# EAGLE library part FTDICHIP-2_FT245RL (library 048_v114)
USB FIFO Controller 4th Generation USB Controller (USB <-> Parallel) - FIFO
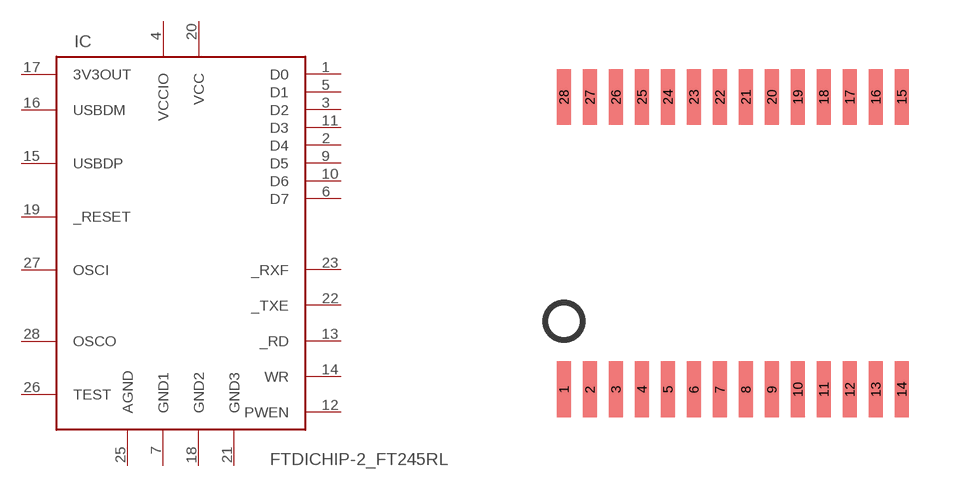
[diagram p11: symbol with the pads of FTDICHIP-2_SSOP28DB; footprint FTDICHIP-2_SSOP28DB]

Designator prefix IC

## FTDICHIP-2_FT245RL  [FTDICHIP-2_SSOP28DB]
1  D0  out
2  D4  out
3  D2  out
4  VCCIO  pwr
5  D1  in
6  D7  in
7  GND1  pwr
9  D5  in
10  D6  in
11  D3  in
12  PWEN
13  _RD
14  WR
15  USBDP
16  USBDM
17  3V3OUT  pwr
18  GND2  pwr
19  _RESET
20  VCC  pwr
21  GND3  pwr
22  _TXE
23  _RXF
25  AGND  pwr
26  TEST  in
27  OSCI
28  OSCO  out

## Footprint FTDICHIP-2_SSOP28DB (pad centres in mm)
Small Shrink Outline Package 28 pin
smd 0.348 x 1.397: 1 -4.225,-3.656; 2 -3.575,-3.656; 3 -2.925,-3.656; 4 -2.275,-3.656; 5 -1.625,-3.656; 6 -0.975,-3.656; 7 -0.325,-3.656; 8 0.325,-3.656; 9 0.975,-3.656; 10 1.625,-3.656; 11 2.275,-3.656; 12 2.925,-3.656; 13 3.575,-3.656; 14 4.225,-3.656; 15 4.225,3.656; 16 3.575,3.656; 17 2.925,3.656; 18 2.275,3.656; 19 1.625,3.656; 20 0.975,3.656; 21 0.325,3.656; 22 -0.325,3.656; 23 -0.975,3.656; 24 -1.625,3.656; 25 -2.275,3.656; 26 -2.925,3.656; 27 -3.575,3.656; 28 -4.225,3.656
